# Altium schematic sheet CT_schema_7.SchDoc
size 277 x 170 mm
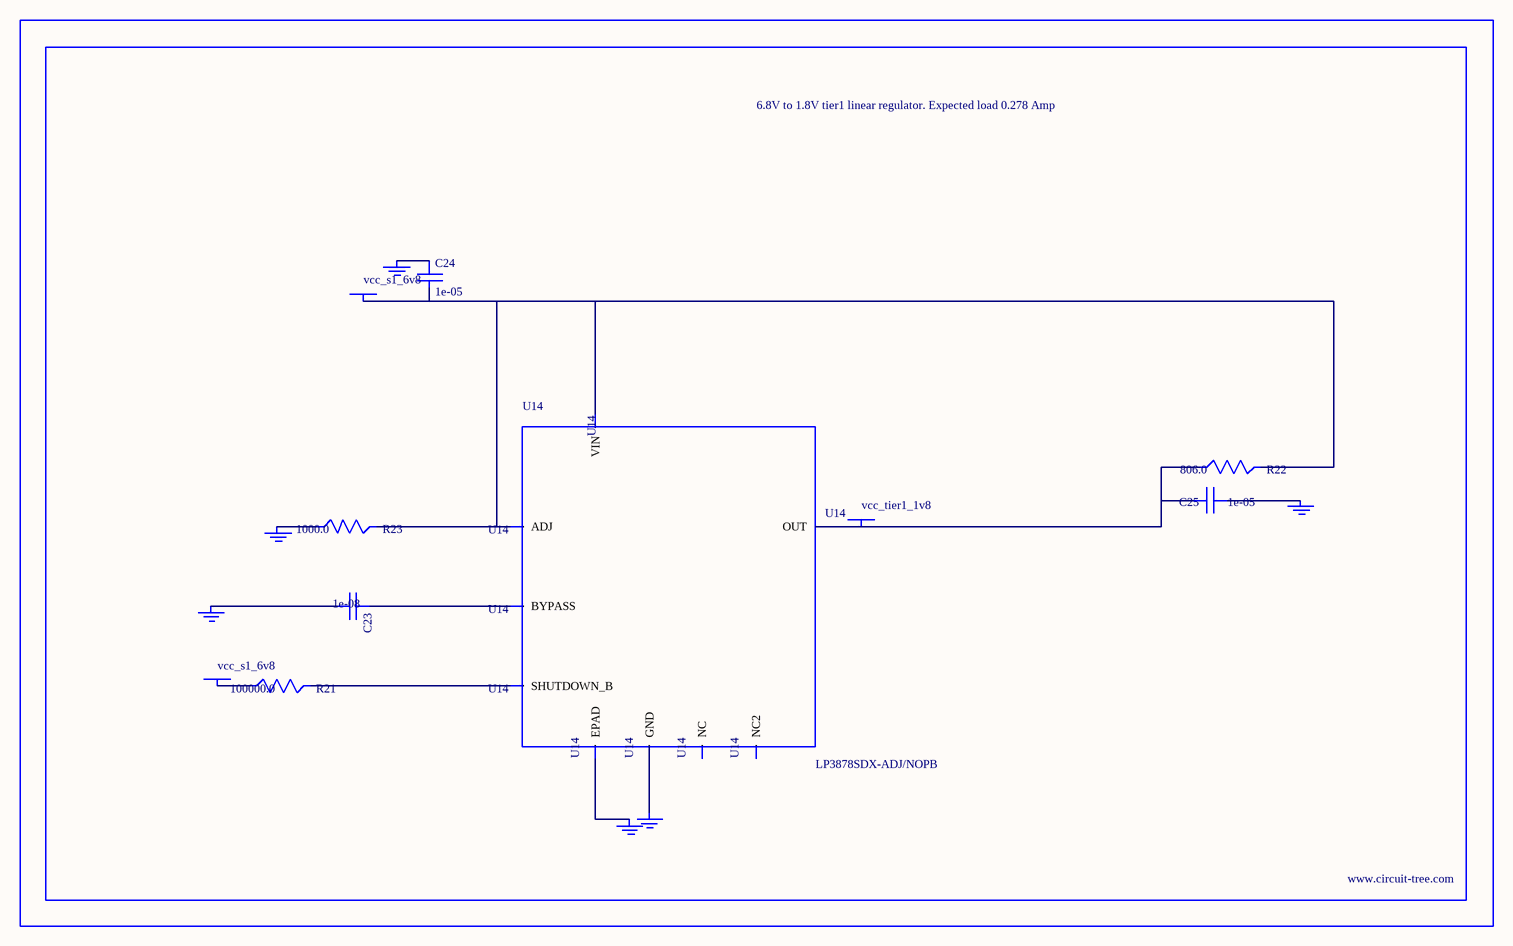
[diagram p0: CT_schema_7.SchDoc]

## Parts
BORDER6  (no value)
C23  1e-08  [C0402]
C24  1e-05  [C1206]
C25  1e-05  [C0805]
GND_INSTANCE_6_0  (no value)
GND_INSTANCE_6_1  (no value)
GND_INSTANCE_6_2  (no value)
GND_INSTANCE_6_3  (no value)
GND_INSTANCE_6_4  (no value)
GND_INSTANCE_6_5  (no value)
POWER_INSTANCE_6_0  vcc_s1_6v8
POWER_INSTANCE_6_1  vcc_s1_6v8
POWER_INSTANCE_6_2  vcc_tier1_1v8
R21  100000.0  [R0603]
R22  806.0  [R0603]
R23  1000.0  [R0603]
U14  LP3878SDX-ADJ/NOPB  [WSON-8]

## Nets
NetC23_1: C23.1 U14.1(BYPASS)
NetC23_2: C23.2 GND_INSTANCE_6_0.0(GND)
NetC24_1: C24.1 GND_INSTANCE_6_1.0(GND)
NetC24_2: C24.2 POWER_INSTANCE_6_0.0(PWR) R22.2 R23.2 U14.4(VIN) U14.6(ADJ)
NetC25_1: C25.1 GND_INSTANCE_6_2.0(GND)
NetC25_2: C25.2 POWER_INSTANCE_6_2.0(PWR) R22.1 U14.5(OUT)
NetGND_INSTANCE_6_3_0: GND_INSTANCE_6_3.0(GND) R23.1
NetGND_INSTANCE_6_4_0: GND_INSTANCE_6_4.0(GND) U14.PAD(EPAD)
NetGND_INSTANCE_6_5_0: GND_INSTANCE_6_5.0(GND) U14.3(GND)
NetPOWER_INSTANCE_6_1_0: POWER_INSTANCE_6_1.0(PWR) R21.1
NetR21_2: R21.2 U14.8(SHUTDOWN_B)

Not connected (* = marked no-connect by the designer): U14 2(NC) 7(NC2)

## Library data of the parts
BORDER6 = BORDER_PAGE6
C23 = C0402C103K3RAC
C24 = C1206C106K3RACTU
C25 = GRM219R60J106ME19D
GND_INSTANCE_6_0-GND_INSTANCE_6_5 = GND
POWER_INSTANCE_6_0-POWER_INSTANCE_6_2 = PWR
R21 = RC0603JR-07100KL
R22 = ERJ-3EKF8060V
R23 = RC0603JR-071KL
